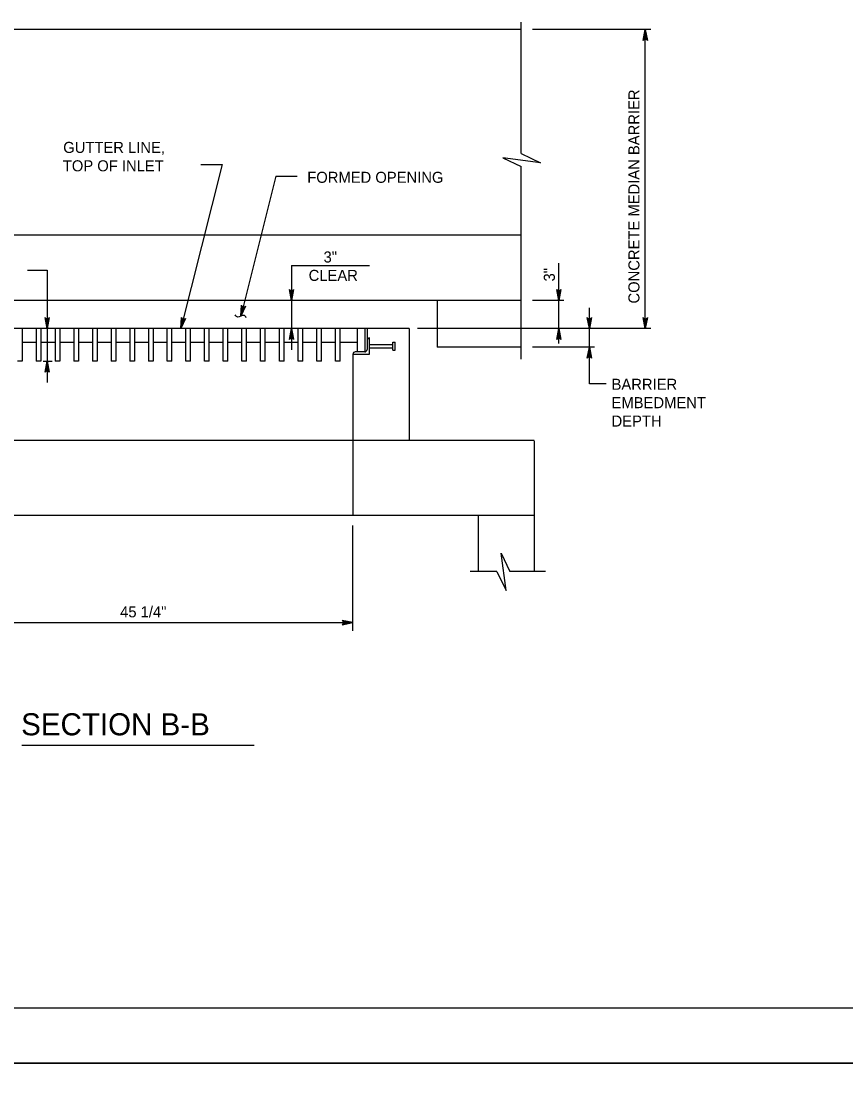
# Model space of a CAD drawing. Extents: x 2087776 to 2104538, y 970919 to 982612.
# Drawn here: x 2091213 to 2091948, y 972844 to 973797 of the extents above; entities that cross this region are included whole.
import ezdxf

# ---------------------------------------------------------------- set-up
doc = ezdxf.new("R2010")
doc.units = 0
doc.layers.add('1', color=7, linetype='Continuous')
doc.layers.add('PLT-BNDY', color=7, linetype='Continuous')

msp = doc.modelspace()

# ---------------------------------------------------------------- linework, layer by layer
at = {"layer": '1'}
for p, q in [((2091658.81, 973679.01), (2091658.81, 973796.07)), ((2091658.81, 973789.59), (2090741.53, 973789.59)), ((2091774.25, 973789.59), (2091668.71, 973789.59)), ((2091769.35, 973522.92), (2091769.35, 973789.59)), ((2091392.18, 973669.06), (2091355.42, 973522.92)), ((2091373.27, 973669.06), (2091392.18, 973669.06)), ((2091440.19, 973658.69), (2091408.8, 973533.9)), ((2091440.19, 973658.69), (2091459.11, 973658.69)), ((2091658.81, 973495.78), (2091658.81, 973667.47)), ((2091658.81, 973606.25), (2090741.53, 973606.25)), ((2091218.73, 973574.93), (2091236.19, 973574.93)), ((2091236.19, 973574.93), (2091236.19, 973474.97)), ((2091454.09, 973579.22), (2091454.09, 973504.11)), ((2091454.09, 973579.22), (2091523.57, 973579.22)), ((2091692.33, 973509.6), (2091692.33, 973581.38)), ((2091658.81, 973547.92), (2090741.53, 973547.92)), ((2091583.81, 973547.92), (2091583.81, 973506.25)), ((2091696.76, 973547.92), (2091668.71, 973547.92)), ((2091696.24, 973547.92), (2091668.71, 973547.92)), ((2091719.52, 973473.75), (2091719.52, 973541.55)), ((2091558.81, 973522.92), (2091081.73, 973522.92)), ((2091214.04, 973522.92), (2091214.04, 973493.75)), ((2091226.54, 973522.92), (2091226.54, 973493.75)), ((2091230.71, 973522.92), (2091230.71, 973493.75)), ((2091243.21, 973522.92), (2091243.21, 973493.75)), ((2091247.38, 973522.92), (2091247.38, 973493.75)), ((2091259.88, 973522.92), (2091259.88, 973493.75)), ((2091264.05, 973522.92), (2091264.05, 973493.75)), ((2091276.55, 973522.92), (2091276.55, 973493.75)), ((2091280.72, 973522.92), (2091280.72, 973493.75)), ((2091293.22, 973522.92), (2091293.22, 973493.75)), ((2091297.39, 973522.92), (2091297.39, 973493.75)), ((2091309.89, 973522.92), (2091309.89, 973493.75)), ((2091314.06, 973522.92), (2091314.06, 973493.75)), ((2091326.56, 973522.92), (2091326.56, 973493.75)), ((2091330.73, 973522.92), (2091330.73, 973493.75)), ((2091343.15, 973493.75), (2091343.15, 973522.92)), ((2091347.32, 973493.75), (2091347.32, 973522.92)), ((2091359.82, 973493.75), (2091359.82, 973522.92)), ((2091363.99, 973493.75), (2091363.99, 973522.92)), ((2091376.49, 973493.75), (2091376.49, 973522.92)), ((2091380.66, 973493.75), (2091380.66, 973522.92)), ((2091393.16, 973493.75), (2091393.16, 973522.92)), ((2091397.33, 973493.75), (2091397.33, 973522.92)), ((2091409.83, 973493.75), (2091409.83, 973522.92)), ((2091414, 973493.75), (2091414, 973522.92)), ((2091426.5, 973493.75), (2091426.5, 973522.92)), ((2091430.67, 973493.75), (2091430.67, 973522.92)), ((2091443.17, 973493.75), (2091443.17, 973522.92)), ((2091447.34, 973493.75), (2091447.34, 973522.92)), ((2091459.84, 973493.75), (2091459.84, 973522.92)), ((2091464.01, 973493.75), (2091464.01, 973522.92)), ((2091476.51, 973493.75), (2091476.51, 973522.92)), ((2091480.68, 973493.75), (2091480.68, 973522.92)), ((2091493.18, 973493.75), (2091493.18, 973522.92)), ((2091497.35, 973493.75), (2091497.35, 973522.92)), ((2091512.98, 973502.08), (2091512.98, 973522.92)), ((2091519.23, 973522.92), (2091519.23, 973502.08)), ((2091521.31, 973522.92), (2091521.31, 973512.51)), ((2091521.31, 973522.92), (2091521.31, 973512.51)), ((2091558.81, 973522.92), (2091558.81, 973423.09)), ((2091774.25, 973522.92), (2091566.33, 973522.92)), ((2091226.54, 973510.42), (2091214.04, 973510.42)), ((2091243.21, 973510.42), (2091230.71, 973510.42)), ((2091259.88, 973510.42), (2091247.38, 973510.42)), ((2091276.55, 973510.42), (2091264.05, 973510.42)), ((2091293.22, 973510.42), (2091280.72, 973510.42)), ((2091309.89, 973510.42), (2091297.39, 973510.42)), ((2091326.56, 973510.42), (2091314.06, 973510.42)), ((2091343.15, 973510.42), (2091330.73, 973510.42)), ((2091359.82, 973510.42), (2091347.32, 973510.42)), ((2091376.49, 973510.42), (2091363.99, 973510.42)), ((2091393.16, 973510.42), (2091380.66, 973510.42)), ((2091409.83, 973510.42), (2091397.33, 973510.42)), ((2091426.5, 973510.42), (2091414, 973510.42)), ((2091443.17, 973510.42), (2091430.67, 973510.42)), ((2091459.84, 973510.42), (2091447.34, 973510.42)), ((2091476.51, 973510.42), (2091464.01, 973510.42)), ((2091493.18, 973510.42), (2091480.68, 973510.42)), ((2091512.98, 973510.42), (2091497.35, 973510.42)), ((2091521.31, 973512.51), (2091521.31, 973504.18)), ((2091523.4, 973500.01), (2091523.4, 973514.59)), ((2091523.4, 973508.86), (2091544.31, 973508.86)), ((2091544.31, 973503.74), (2091544.31, 973510.86)), ((2091544.31, 973510.86), (2091546.31, 973510.86)), ((2091546.31, 973503.74), (2091546.31, 973510.86)), ((2091658.81, 973506.25), (2091583.81, 973506.25)), ((2091724.22, 973506.25), (2091668.71, 973506.25)), ((2091724.22, 973506.25), (2091668.71, 973506.25)), ((2091508.81, 973500.01), (2091508.81, 973423.09)), ((2091508.81, 973500.01), (2091523.4, 973500.01)), ((2091519.23, 973502.09), (2091510.89, 973502.09)), ((2091523.4, 973505.74), (2091544.31, 973505.74)), ((2091544.31, 973503.74), (2091546.31, 973503.74)), ((2091214.04, 973493.75), (2091209.87, 973493.75)), ((2091230.71, 973493.75), (2091226.54, 973493.75)), ((2091232.76, 973493.75), (2091240.6, 973493.75)), ((2091247.38, 973493.75), (2091243.21, 973493.75)), ((2091264.05, 973493.75), (2091259.88, 973493.75)), ((2091280.72, 973493.75), (2091276.55, 973493.75)), ((2091297.39, 973493.75), (2091293.22, 973493.75)), ((2091314.06, 973493.75), (2091309.89, 973493.75)), ((2091330.73, 973493.75), (2091326.56, 973493.75)), ((2091347.32, 973493.75), (2091343.15, 973493.75)), ((2091363.99, 973493.75), (2091359.82, 973493.75)), ((2091380.66, 973493.75), (2091376.49, 973493.75)), ((2091397.33, 973493.75), (2091393.16, 973493.75)), ((2091414, 973493.75), (2091409.83, 973493.75)), ((2091430.67, 973493.75), (2091426.5, 973493.75)), ((2091447.34, 973493.75), (2091443.17, 973493.75)), ((2091464.01, 973493.75), (2091459.84, 973493.75)), ((2091480.68, 973493.75), (2091476.51, 973493.75)), ((2091497.35, 973493.75), (2091493.18, 973493.75)), ((2091734.41, 973473.75), (2091719.52, 973473.75)), ((2091670.27, 973423.09), (2090970.27, 973423.09)), ((2091508.81, 973423.09), (2091508.81, 973356.42)), ((2091670.27, 973422.92), (2091670.27, 973306.42)), ((2091670.27, 973356.42), (2090970.27, 973356.42)), ((2091620.27, 973356.42), (2091620.27, 973306.42)), ((2091508.81, 973253.32), (2091508.81, 973347.36)), ((2091637.08, 973306.42), (2091613.18, 973306.42)), ((2091680.32, 973306.42), (2091648.63, 973306.42)), ((2091131.73, 973260.76), (2091508.81, 973260.76)), ((2091213.67, 973151.58), (2091420.59, 973151.58))]:
    msp.add_line(p, q, dxfattribs=at)
for points in [[(2093241.55, 972917.37), (2093241.55, 974767.76), (2090662.81, 974767.76), (2090662.81, 972917.37), (2093241.55, 972917.37), (2093241.55, 973003.85), (2092585.39, 973003.85), (2092585.39, 973216.04), (2093241.55, 973216.04), (2093241.55, 973311.07), (2092585.39, 973311.07), (2092585.39, 972917.37), (2092843.92, 972917.37), (2092843.92, 973003.85), (2092843.92, 972917.37), (2093096.55, 972917.37), (2093096.55, 973003.85), (2093096.55, 972963.44), (2093241.55, 972963.44)], [(2091769.35, 973789.59), (2091771.19, 973779.81), (2091770.92, 973780.19), (2091770.66, 973780.56), (2091770.34, 973780.76), (2091770.01, 973780.95), (2091769.68, 973781.01), (2091769.35, 973781.06), (2091769.02, 973781.01), (2091768.69, 973780.95), (2091768.37, 973780.76), (2091768.04, 973780.56), (2091767.78, 973780.19), (2091767.52, 973779.81), (2091769.35, 973789.59), (2091767.78, 973780.19), (2091768.04, 973780.56), (2091769.35, 973789.59), (2091768.37, 973780.76), (2091768.69, 973780.95), (2091769.35, 973789.59), (2091769.02, 973781.01), (2091769.35, 973781.06), (2091769.35, 973789.59), (2091769.68, 973781.01), (2091770.01, 973780.95), (2091769.35, 973789.59), (2091770.34, 973780.76), (2091770.66, 973780.56), (2091769.35, 973789.59), (2091770.92, 973780.19)], [(2091658.81, 973679.01), (2091675.83, 973670.68), (2091642.53, 973675.21), (2091658.81, 973667.47)], [(2091454.09, 973547.92), (2091452.26, 973557.71), (2091452.52, 973557.33), (2091452.78, 973556.96), (2091453.11, 973556.76), (2091453.43, 973556.57), (2091453.76, 973556.51), (2091454.09, 973556.46), (2091454.42, 973556.51), (2091454.75, 973556.57), (2091455.08, 973556.76), (2091455.4, 973556.96), (2091455.66, 973557.33), (2091455.93, 973557.71), (2091454.09, 973547.92), (2091455.66, 973557.33), (2091455.4, 973556.96), (2091454.09, 973547.92), (2091455.08, 973556.76), (2091454.75, 973556.57), (2091454.09, 973547.92), (2091454.42, 973556.51), (2091454.09, 973556.46), (2091454.09, 973547.92), (2091453.76, 973556.51), (2091453.43, 973556.57), (2091454.09, 973547.92), (2091453.11, 973556.76), (2091452.78, 973556.96), (2091454.09, 973547.92), (2091452.52, 973557.33)], [(2091692.33, 973547.92), (2091690.5, 973557.71), (2091690.76, 973557.33), (2091691.02, 973556.96), (2091691.35, 973556.76), (2091691.68, 973556.57), (2091692.01, 973556.51), (2091692.33, 973556.46), (2091692.66, 973556.51), (2091692.99, 973556.57), (2091693.32, 973556.76), (2091693.65, 973556.96), (2091693.91, 973557.33), (2091694.17, 973557.71), (2091692.33, 973547.92), (2091693.91, 973557.33), (2091693.65, 973556.96), (2091692.33, 973547.92), (2091693.32, 973556.76), (2091692.99, 973556.57), (2091692.33, 973547.92), (2091692.66, 973556.51), (2091692.33, 973556.46), (2091692.33, 973547.92), (2091692.01, 973556.51), (2091691.68, 973556.57), (2091692.33, 973547.92), (2091691.35, 973556.76), (2091691.02, 973556.96), (2091692.33, 973547.92), (2091690.76, 973557.33)], [(2091408.8, 973533.9), (2091409.41, 973543.84), (2091409.57, 973543.41), (2091409.73, 973542.98), (2091410.01, 973542.71), (2091410.28, 973542.44), (2091410.58, 973542.31), (2091410.89, 973542.17), (2091411.22, 973542.15), (2091411.55, 973542.12), (2091411.91, 973542.23), (2091412.28, 973542.34), (2091412.63, 973542.64), (2091412.97, 973542.94), (2091408.8, 973533.9), (2091412.63, 973542.64), (2091412.28, 973542.34), (2091408.8, 973533.9), (2091411.91, 973542.23), (2091411.55, 973542.12), (2091408.8, 973533.9), (2091411.22, 973542.15), (2091410.89, 973542.17), (2091408.8, 973533.9), (2091410.58, 973542.31), (2091410.28, 973542.44), (2091408.8, 973533.9), (2091410.01, 973542.71), (2091409.73, 973542.98), (2091408.8, 973533.9), (2091409.57, 973543.41)], [(2091236.19, 973522.92), (2091234.36, 973532.71), (2091234.62, 973532.33), (2091234.88, 973531.96), (2091235.21, 973531.76), (2091235.53, 973531.57), (2091235.86, 973531.51), (2091236.19, 973531.46), (2091236.52, 973531.51), (2091236.85, 973531.57), (2091237.17, 973531.76), (2091237.5, 973531.96), (2091237.76, 973532.33), (2091238.03, 973532.71), (2091236.19, 973522.92), (2091237.76, 973532.33), (2091237.5, 973531.96), (2091236.19, 973522.92), (2091237.17, 973531.76), (2091236.85, 973531.57), (2091236.19, 973522.92), (2091236.52, 973531.51), (2091236.19, 973531.46), (2091236.19, 973522.92), (2091235.86, 973531.51), (2091235.53, 973531.57), (2091236.19, 973522.92), (2091235.21, 973531.76), (2091234.88, 973531.96), (2091236.19, 973522.92), (2091234.62, 973532.33)], [(2091355.42, 973522.92), (2091356.03, 973532.86), (2091356.19, 973532.43), (2091356.35, 973532), (2091356.62, 973531.74), (2091356.89, 973531.47), (2091357.2, 973531.33), (2091357.5, 973531.2), (2091357.84, 973531.17), (2091358.17, 973531.15), (2091358.53, 973531.25), (2091358.9, 973531.36), (2091359.24, 973531.67), (2091359.59, 973531.97), (2091355.42, 973522.92), (2091359.24, 973531.67), (2091358.9, 973531.36), (2091355.42, 973522.92), (2091358.53, 973531.25), (2091358.17, 973531.15), (2091355.42, 973522.92), (2091357.84, 973531.17), (2091357.5, 973531.2), (2091355.42, 973522.92), (2091357.2, 973531.33), (2091356.89, 973531.47), (2091355.42, 973522.92), (2091356.62, 973531.74), (2091356.35, 973532), (2091355.42, 973522.92), (2091356.19, 973532.43)], [(2091719.52, 973522.92), (2091717.68, 973532.71), (2091717.94, 973532.33), (2091718.21, 973531.96), (2091718.53, 973531.76), (2091718.86, 973531.57), (2091719.19, 973531.51), (2091719.52, 973531.46), (2091719.85, 973531.51), (2091720.17, 973531.57), (2091720.5, 973531.76), (2091720.83, 973531.96), (2091721.09, 973532.33), (2091721.35, 973532.71), (2091719.52, 973522.92), (2091721.09, 973532.33), (2091720.83, 973531.96), (2091719.52, 973522.92), (2091720.5, 973531.76), (2091720.17, 973531.57), (2091719.52, 973522.92), (2091719.85, 973531.51), (2091719.52, 973531.46), (2091719.52, 973522.92), (2091719.19, 973531.51), (2091718.86, 973531.57), (2091719.52, 973522.92), (2091718.53, 973531.76), (2091718.21, 973531.96), (2091719.52, 973522.92), (2091717.94, 973532.33)], [(2091769.35, 973522.92), (2091767.52, 973532.71), (2091767.78, 973532.33), (2091768.04, 973531.96), (2091768.37, 973531.76), (2091768.69, 973531.57), (2091769.02, 973531.51), (2091769.35, 973531.46), (2091769.68, 973531.51), (2091770.01, 973531.57), (2091770.34, 973531.76), (2091770.66, 973531.96), (2091770.92, 973532.33), (2091771.19, 973532.71), (2091769.35, 973522.92), (2091770.92, 973532.33), (2091770.66, 973531.96), (2091769.35, 973522.92), (2091770.34, 973531.76), (2091770.01, 973531.57), (2091769.35, 973522.92), (2091769.68, 973531.51), (2091769.35, 973531.46), (2091769.35, 973522.92), (2091769.02, 973531.51), (2091768.69, 973531.57), (2091769.35, 973522.92), (2091768.37, 973531.76), (2091768.04, 973531.96), (2091769.35, 973522.92), (2091767.78, 973532.33)], [(2091454.09, 973522.92), (2091455.93, 973513.14), (2091455.66, 973513.52), (2091455.4, 973513.89), (2091455.08, 973514.09), (2091454.75, 973514.28), (2091454.42, 973514.34), (2091454.09, 973514.39), (2091453.76, 973514.34), (2091453.43, 973514.28), (2091453.11, 973514.09), (2091452.78, 973513.89), (2091452.52, 973513.52), (2091452.26, 973513.14), (2091454.09, 973522.92), (2091452.52, 973513.52), (2091452.78, 973513.89), (2091454.09, 973522.92), (2091453.11, 973514.09), (2091453.43, 973514.28), (2091454.09, 973522.92), (2091453.76, 973514.34), (2091454.09, 973514.39), (2091454.09, 973522.92), (2091454.42, 973514.34), (2091454.75, 973514.28), (2091454.09, 973522.92), (2091455.08, 973514.09), (2091455.4, 973513.89), (2091454.09, 973522.92), (2091455.66, 973513.52)], [(2091692.33, 973522.92), (2091694.17, 973513.14), (2091693.91, 973513.52), (2091693.65, 973513.89), (2091693.32, 973514.09), (2091692.99, 973514.28), (2091692.66, 973514.34), (2091692.33, 973514.39), (2091692.01, 973514.34), (2091691.68, 973514.28), (2091691.35, 973514.09), (2091691.02, 973513.89), (2091690.76, 973513.52), (2091690.5, 973513.14), (2091692.33, 973522.92), (2091690.76, 973513.52), (2091691.02, 973513.89), (2091692.33, 973522.92), (2091691.35, 973514.09), (2091691.68, 973514.28), (2091692.33, 973522.92), (2091692.01, 973514.34), (2091692.33, 973514.39), (2091692.33, 973522.92), (2091692.66, 973514.34), (2091692.99, 973514.28), (2091692.33, 973522.92), (2091693.32, 973514.09), (2091693.65, 973513.89), (2091692.33, 973522.92), (2091693.91, 973513.52)], [(2091719.52, 973506.25), (2091721.35, 973496.47), (2091721.09, 973496.85), (2091720.83, 973497.22), (2091720.5, 973497.42), (2091720.17, 973497.61), (2091719.85, 973497.67), (2091719.52, 973497.72), (2091719.19, 973497.67), (2091718.86, 973497.61), (2091718.53, 973497.42), (2091718.21, 973497.22), (2091717.94, 973496.85), (2091717.68, 973496.47), (2091719.52, 973506.25), (2091717.94, 973496.85), (2091718.21, 973497.22), (2091719.52, 973506.25), (2091718.53, 973497.42), (2091718.86, 973497.61), (2091719.52, 973506.25), (2091719.19, 973497.67), (2091719.52, 973497.72), (2091719.52, 973506.25), (2091719.85, 973497.67), (2091720.17, 973497.61), (2091719.52, 973506.25), (2091720.5, 973497.42), (2091720.83, 973497.22), (2091719.52, 973506.25), (2091721.09, 973496.85)], [(2091236.19, 973493.75), (2091238.03, 973483.97), (2091237.76, 973484.35), (2091237.5, 973484.72), (2091237.17, 973484.92), (2091236.85, 973485.11), (2091236.52, 973485.17), (2091236.19, 973485.22), (2091235.86, 973485.17), (2091235.53, 973485.11), (2091235.21, 973484.92), (2091234.88, 973484.72), (2091234.62, 973484.35), (2091234.36, 973483.97), (2091236.19, 973493.75), (2091234.62, 973484.35), (2091234.88, 973484.72), (2091236.19, 973493.75), (2091235.21, 973484.92), (2091235.53, 973485.11), (2091236.19, 973493.75), (2091235.86, 973485.17), (2091236.19, 973485.22), (2091236.19, 973493.75), (2091236.52, 973485.17), (2091236.85, 973485.11), (2091236.19, 973493.75), (2091237.17, 973484.92), (2091237.5, 973484.72), (2091236.19, 973493.75), (2091237.76, 973484.35)], [(2091637.09, 973306.42), (2091645.41, 973289.41), (2091640.89, 973322.7), (2091648.63, 973306.42)], [(2091508.81, 973260.76), (2091499.03, 973262.59), (2091499.4, 973262.33), (2091499.78, 973262.07), (2091499.98, 973261.74), (2091500.17, 973261.41), (2091500.23, 973261.08), (2091500.28, 973260.76), (2091500.23, 973260.43), (2091500.17, 973260.1), (2091499.98, 973259.77), (2091499.78, 973259.44), (2091499.4, 973259.18), (2091499.03, 973258.92), (2091508.81, 973260.76), (2091499.4, 973259.18), (2091499.78, 973259.44), (2091508.81, 973260.76), (2091499.98, 973259.77), (2091500.17, 973260.1), (2091508.81, 973260.76), (2091500.23, 973260.43), (2091500.28, 973260.76), (2091508.81, 973260.76), (2091500.23, 973261.08), (2091500.17, 973261.41), (2091508.81, 973260.76), (2091499.98, 973261.74), (2091499.78, 973262.07), (2091508.81, 973260.76), (2091499.4, 973262.33)]]:
    msp.add_lwpolyline(points, dxfattribs=at)
for centre, start, end in [((2091523.4, 973512.51), 90, 180), ((2091510.89, 973500.01), 90, 180), ((2091519.23, 973504.18), 270, 0)]:
    msp.add_arc(centre, 2.08, start, end, dxfattribs=at)
msp.add_spline([(2091413.74, 973532.55), (2091411.36, 973534.71), (2091406.22, 973533.08), (2091403.84, 973535.08)], degree=3, dxfattribs=at)
at = {"layer": 'PLT-BNDY'}
for points in [[(2090534.86, 974816.97), (2093294.05, 974816.97), (2093294.05, 972868.16), (2090534.86, 972868.16)], [(2090534.86, 972868.16), (2093294.05, 972868.16), (2093294.05, 970919.34), (2090534.86, 970919.34)]]:
    msp.add_lwpolyline(points, close=True, dxfattribs=at)

# ---------------------------------------------------------------- texts
at = {"layer": '1'}
for s, height, p in [('CONCRETE MEDIAN BARRIER', 9.8425, (2091764.15, 973545.26)), ('3"', 9.843, (2091688.76, 973564.93))]:
    msp.add_text(s, height=height, rotation=90, dxfattribs=at).set_placement(p)
for s, height, p in [('GUTTER LINE,', 9.8425, (2091250.53, 973679.52)), ('TOP OF INLET', 9.8425, (2091250.18, 973663.12)), ('FORMED OPENING', 9.8425, (2091468.06, 973652.87)), ('3"', 9.843, (2091482.6, 973581.83)), ('CLEAR', 9.843, (2091469.3, 973565.42)), ('BARRIER', 9.843, (2091739.31, 973468.36)), ('EMBEDMENT', 9.843, (2091739.31, 973451.96)), ('DEPTH', 9.843, (2091739.31, 973435.55)), ('45 1/4"', 9.843, (2091301.26, 973265.48)), ('SECTION B-B', 19.685, (2091213.02, 973160.29))]:
    msp.add_text(s, height=height, dxfattribs=at).set_placement(p)

doc.saveas('drawing.dxf')
